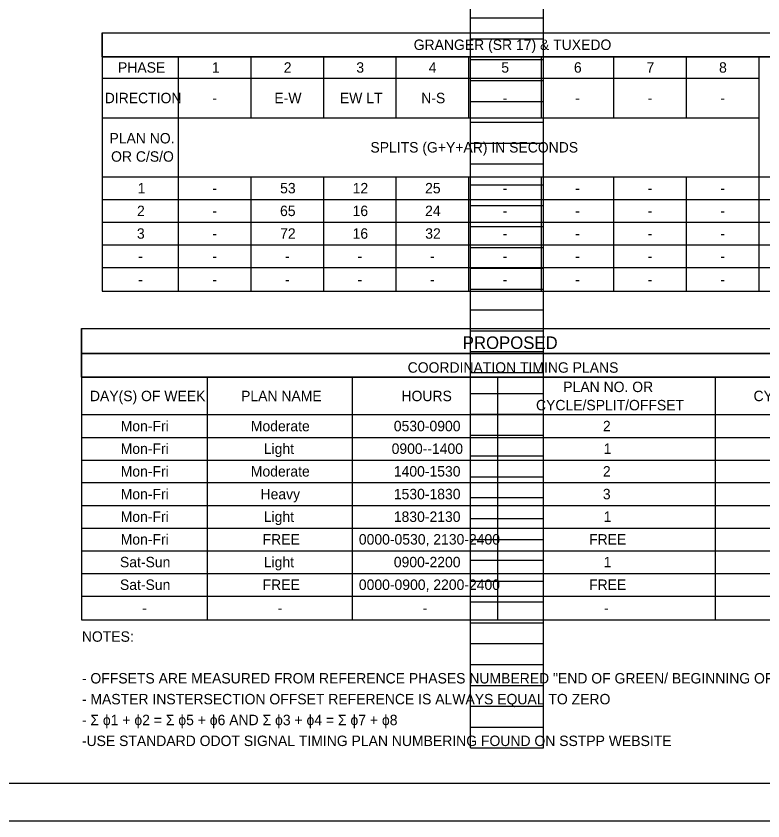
# Model space of a CAD drawing. Extents: x -18.6 to 78.7, y 0 to 36.9.
# Drawn here: x 17.58 to 27.6, y 0 to 10.8 of the extents above; entities that cross this region are included whole.
import ezdxf

# ---------------------------------------------------------------- set-up
doc = ezdxf.new("R2010")
doc.units = 0
for name, color, linetype in [('SH_Border', 7, 'Continuous'), ('SH_Cut_Line', 7, 'Continuous'), ('SH_Data', 7, 'Continuous'), ('SH_Text', 7, 'Continuous')]:
    doc.layers.add(name, color=color, linetype=linetype)

msp = doc.modelspace()

# ---------------------------------------------------------------- linework, layer by layer
at = {"layer": 'SH_Border'}
msp.add_lwpolyline([(1.5, 21.5), (33.5, 21.5), (33.5, 0.5), (1.5, 0.5)], close=True, dxfattribs=at)
at = {"layer": 'SH_Cut_Line'}
msp.add_lwpolyline([(0, 0), (34, 0), (34, 22), (0, 22)], close=True, dxfattribs=at)
at = {"layer": 'SH_Data'}
for p, q in [((23.68, 0.98), (23.68, 21.14)), ((24.66, 0.98), (24.66, 21.14)), ((23.68, 10.78), (24.66, 10.78)), ((23.68, 10.5), (24.66, 10.5)), ((23.68, 10.22), (24.66, 10.22)), ((23.68, 9.94), (24.66, 9.94)), ((23.68, 9.66), (24.66, 9.66)), ((23.68, 9.38), (24.66, 9.38)), ((23.68, 9.1), (24.66, 9.1)), ((23.68, 8.82), (24.66, 8.82)), ((23.68, 8.54), (24.66, 8.54)), ((23.68, 8.26), (24.66, 8.26)), ((23.68, 7.98), (24.66, 7.98)), ((23.68, 7.7), (24.66, 7.7)), ((23.68, 7.42), (24.66, 7.42)), ((23.68, 7.14), (24.66, 7.14)), ((23.68, 6.86), (24.66, 6.86)), ((23.68, 6.58), (24.66, 6.58)), ((23.68, 6.3), (24.66, 6.3)), ((23.68, 6.02), (24.66, 6.02)), ((23.68, 5.74), (24.66, 5.74)), ((23.68, 5.46), (24.66, 5.46)), ((23.68, 5.18), (24.66, 5.18)), ((23.68, 4.9), (24.66, 4.9)), ((23.68, 4.62), (24.66, 4.62)), ((23.68, 4.34), (24.66, 4.34)), ((23.68, 4.06), (24.66, 4.06)), ((23.68, 3.78), (24.66, 3.78)), ((23.68, 3.5), (24.66, 3.5)), ((23.68, 3.22), (24.66, 3.22)), ((23.68, 2.94), (24.66, 2.94)), ((23.68, 2.66), (24.66, 2.66)), ((23.68, 2.38), (24.66, 2.38)), ((23.68, 2.1), (24.66, 2.1)), ((23.68, 1.82), (24.66, 1.82)), ((23.68, 1.54), (24.66, 1.54)), ((23.68, 1.26), (24.66, 1.26)), ((23.68, 0.98), (24.66, 0.98))]:
    msp.add_line(p, q, dxfattribs=at)
at = {"layer": 'SH_Text'}
for p, q in [((18.737, 10.58), (29.603, 10.58)), ((18.737, 10.58), (18.737, 7.11)), ((18.737, 10.26), (29.603, 10.26)), ((19.757, 10.26), (19.757, 7.11)), ((20.731, 10.26), (20.731, 9.438)), ((21.705, 10.26), (21.705, 9.438)), ((22.679, 10.26), (22.679, 9.438)), ((23.653, 10.26), (23.653, 9.438)), ((24.627, 10.26), (24.627, 9.438)), ((25.6, 10.26), (25.6, 9.438)), ((26.574, 10.26), (26.574, 9.438)), ((27.548, 10.26), (27.548, 7.11)), ((18.737, 9.971), (27.548, 9.971)), ((18.737, 9.438), (19.757, 9.438)), ((19.757, 9.438), (27.548, 9.438)), ((18.737, 8.647), (29.603, 8.647)), ((20.731, 8.647), (20.731, 7.11)), ((21.705, 8.647), (21.705, 7.11)), ((22.679, 8.647), (22.679, 7.11)), ((23.653, 8.647), (23.653, 7.11)), ((24.627, 8.647), (24.627, 7.11)), ((25.6, 8.647), (25.6, 7.11)), ((26.574, 8.647), (26.574, 7.11)), ((18.737, 8.343), (29.603, 8.343)), ((18.737, 8.038), (29.603, 8.038)), ((18.737, 7.734), (29.603, 7.734)), ((18.737, 7.43), (29.603, 7.43)), ((18.737, 7.11), (29.603, 7.11)), ((18.456, 6.61), (29.884, 6.61)), ((18.456, 6.61), (18.456, 2.699)), ((18.456, 6.275), (29.884, 6.275)), ((18.456, 5.956), (29.884, 5.956)), ((20.145, 5.956), (20.145, 2.699)), ((22.093, 5.956), (22.093, 2.699)), ((24.041, 5.956), (24.041, 2.699)), ((26.962, 5.956), (26.962, 2.699)), ((18.456, 5.454), (29.884, 5.454)), ((18.456, 5.149), (29.884, 5.149)), ((18.456, 4.845), (29.884, 4.845)), ((18.456, 4.541), (29.884, 4.541)), ((18.456, 4.236), (29.884, 4.236)), ((18.456, 3.932), (29.884, 3.932)), ((18.456, 3.628), (29.884, 3.628)), ((18.456, 3.323), (29.884, 3.323)), ((18.456, 3.019), (29.884, 3.019)), ((18.456, 2.699), (29.884, 2.699))]:
    msp.add_line(p, q, dxfattribs=at)
for points in [[(18.737, 10.58), (29.603, 10.58), (29.603, 10.26), (18.737, 10.26)], [(18.456, 6.61), (29.884, 6.61), (29.884, 6.275), (18.456, 6.275)], [(18.456, 6.275), (29.884, 6.275), (29.884, 5.956), (18.456, 5.956)]]:
    msp.add_lwpolyline(points, close=True, dxfattribs=at)

# ---------------------------------------------------------------- texts
for s, height, p in [('GRANGER (SR 17) & TUXEDO', 0.14, (22.917, 10.35)), ('PHASE', 0.14, (18.948, 10.045)), ('1', 0.14, (20.209, 10.045)), ('2', 0.14, (21.173, 10.045)), ('3', 0.14, (22.147, 10.045)), ('4', 0.14, (23.119, 10.045)), ('5', 0.14, (24.093, 10.045)), ('6', 0.14, (25.068, 10.045)), ('7', 0.14, (26.042, 10.045)), ('8', 0.14, (27.016, 10.045)), ('DIRECTION', 0.14, (18.77, 9.635)), ('E-W', 0.14, (21.047, 9.635)), ('EW LT', 0.14, (21.926, 9.635)), ('N-S', 0.14, (23.018, 9.635)), ('-', 0.14, (20.215, 9.635)), ('-', 0.14, (24.111, 9.635)), ('-', 0.14, (25.085, 9.635)), ('-', 0.14, (26.059, 9.635)), ('-', 0.14, (27.033, 9.635)), ('PLAN NO. ', 0.14, (18.833, 9.095)), ('SPLITS (G+Y+AR) IN SECONDS', 0.14, (22.336, 8.973)), ('OR C/S/O', 0.14, (18.855, 8.85)), ('1', 0.14, (19.213, 8.425)), ('53', 0.14, (21.124, 8.425)), ('12', 0.14, (22.098, 8.425)), ('25', 0.14, (23.07, 8.425)), ('-', 0.14, (20.215, 8.425)), ('-', 0.14, (24.111, 8.425)), ('-', 0.14, (25.085, 8.425)), ('-', 0.14, (26.059, 8.425)), ('-', 0.14, (27.033, 8.425)), ('2', 0.14, (19.203, 8.12)), ('65', 0.14, (21.123, 8.12)), ('16', 0.14, (22.097, 8.12)), ('24', 0.14, (23.07, 8.12)), ('-', 0.14, (20.215, 8.12)), ('-', 0.14, (24.111, 8.12)), ('-', 0.14, (25.085, 8.12)), ('-', 0.14, (26.059, 8.12)), ('-', 0.14, (27.033, 8.12)), ('3', 0.14, (19.202, 7.816)), ('72', 0.14, (21.124, 7.816)), ('16', 0.14, (22.097, 7.816)), ('32', 0.14, (23.072, 7.816)), ('-', 0.14, (20.215, 7.816)), ('-', 0.14, (24.111, 7.816)), ('-', 0.14, (25.085, 7.816)), ('-', 0.14, (26.059, 7.816)), ('-', 0.14, (27.033, 7.816)), ('-', 0.14, (19.219, 7.512)), ('-', 0.14, (20.215, 7.512)), ('-', 0.14, (21.189, 7.512)), ('-', 0.14, (22.163, 7.512)), ('-', 0.14, (23.137, 7.512)), ('-', 0.14, (24.111, 7.512)), ('-', 0.14, (25.085, 7.512)), ('-', 0.14, (26.059, 7.512)), ('-', 0.14, (27.033, 7.512)), ('-', 0.14, (19.219, 7.2)), ('-', 0.14, (20.215, 7.2)), ('-', 0.14, (21.189, 7.2)), ('-', 0.14, (22.163, 7.2)), ('-', 0.14, (23.137, 7.2)), ('-', 0.14, (24.111, 7.2)), ('-', 0.14, (25.085, 7.2)), ('-', 0.14, (26.059, 7.2)), ('-', 0.14, (27.033, 7.2)), ('PROPOSED', 0.168, (23.576, 6.336)), ('COORDINATION TIMING PLANS', 0.13999, (22.836, 6.017)), ('PLAN NO. OR', 0.13999, (24.925, 5.757)), ('DAY(S) OF WEEK', 0.13999, (18.571, 5.635)), ('PLAN NAME', 0.14, (20.6, 5.635)), ('HOURS', 0.14, (22.753, 5.635)), ('CYCLE LENGTH (SEC)', 0.13999, (27.479, 5.635)), ('CYCLE/SPLIT/OFFSET', 0.13999, (24.559, 5.512)), ('Mon-Fri', 0.14, (18.984, 5.231)), ('Moderate', 0.14, (20.731, 5.231)), ('0530-0900', 0.14, (22.65, 5.231)), ('2', 0.14, (25.457, 5.231)), ('Mon-Fri', 0.14, (18.984, 4.927)), ('Light', 0.14, (20.905, 4.927)), ('0900--1400', 0.14, (22.621, 4.927)), ('1', 0.14, (25.467, 4.927)), ('Mon-Fri', 0.14, (18.984, 4.623)), ('Moderate', 0.14, (20.731, 4.623)), ('1400-1530', 0.14, (22.65, 4.623)), ('2', 0.14, (25.457, 4.623)), ('Mon-Fri', 0.14, (18.984, 4.318)), ('Heavy', 0.14, (20.861, 4.318)), ('1530-1830', 0.14, (22.65, 4.318)), ('3', 0.14, (25.456, 4.318)), ('Mon-Fri', 0.14, (18.984, 4.014)), ('Light', 0.14, (20.905, 4.014)), ('1830-2130', 0.14, (22.65, 4.014)), ('1', 0.14, (25.467, 4.014)), ('Mon-Fri', 0.14, (18.984, 3.71)), ('FREE', 0.14, (20.889, 3.71)), ('0000-0530, 2130-2400', 0.13999, (22.181, 3.71)), ('FREE', 0.14, (25.271, 3.71)), ('Sat-Sun', 0.14, (18.974, 3.405)), ('Light', 0.14, (20.905, 3.405)), ('0900-2200', 0.14, (22.65, 3.405)), ('1', 0.14, (25.467, 3.405)), ('Sat-Sun', 0.14, (18.974, 3.101)), ('0000-0900, 2200-2400', 0.13999, (22.181, 3.101)), ('FREE', 0.14, (20.889, 3.101)), ('FREE', 0.14, (25.271, 3.101)), ('-', 0.14, (19.272, 2.789)), ('-', 0.14, (21.09, 2.789)), ('-', 0.14, (23.038, 2.789)), ('-', 0.14, (25.473, 2.789)), ('NOTES:', 0.14, (18.463, 2.405)), ('- OFFSETS ARE MEASURED FROM REFERENCE PHASES NUMBERED "END OF GREEN/ BEGINNING OF YELLOW"', 0.14, (18.463, 1.845)), ('- MASTER INSTERSECTION OFFSET REFERENCE IS ALWAYS EQUAL TO ZERO', 0.14, (18.463, 1.565)), ('- Σ ϕ1 + ϕ2 = Σ ϕ5 + ϕ6 AND Σ ϕ3 + ϕ4 = Σ ϕ7 + ϕ8', 0.14, (18.463, 1.285)), ('-USE STANDARD ODOT SIGNAL TIMING PLAN NUMBERING FOUND ON SSTPP WEBSITE', 0.14, (18.463, 1.005))]:
    msp.add_text(s, height=height, dxfattribs=at).set_placement(p)

doc.saveas('drawing.dxf')
